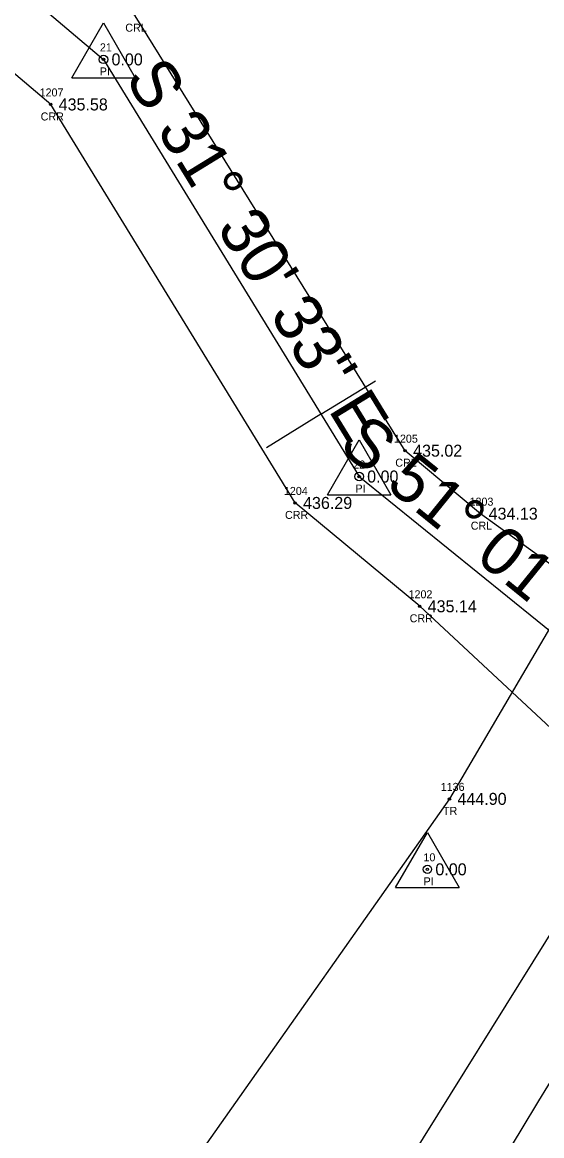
# Model space of a CAD drawing. Extents: x 1762456 to 1764480, y 822234 to 826541.
# Drawn here: x 1763387.7 to 1763452.5, y 824767.8 to 824906.9 of the extents above; entities that cross this region are included whole.
import ezdxf

# ---------------------------------------------------------------- set-up
doc = ezdxf.new("R2010")
doc.units = 0
for name, color, linetype in [('RD_EX_H2O', 7, 'Continuous'), ('RD_EX_H2O_txCode', 7, 'Continuous'), ('RD_EX_Road', 7, 'Continuous'), ('RD_EX_TX_H2O_ELEV', 7, 'Continuous'), ('RD_EX_TX_VEG_ELEV', 7, 'Continuous'), ('RD_EX_VEG', 7, 'Continuous'), ('RD_EX_VEG_txCode', 7, 'Continuous'), ('RD_HC_Cl', 7, 'Continuous'), ('RD_HC_Data', 7, 'Continuous'), ('RD_HC_Data_Tic', 7, 'Continuous'), ('RD_HC_Survey_ELEV', 7, 'Continuous'), ('RD_HC_txCode', 7, 'Continuous'), ('RD_SMD_Locator', 7, 'Continuous')]:
    doc.layers.add(name, color=color, linetype=linetype)

msp = doc.modelspace()

# ---------------------------------------------------------------- linework, layer by layer
at = {"layer": 'RD_EX_H2O'}
for points in [[(1763469.64, 824827.68), (1763444.91, 824845.55), (1763435.48, 824853.42), (1763401.74, 824907.76), (1763323.19, 824974.27), (1763226.75, 825015.18), (1763219.02, 825018.48), (1763206.39, 825014.43), (1763109.02, 824967.64), (1763091.9, 824957.32), (1763081.74, 824947.35), (1763046.14, 824865.15)], [(1763459.77, 824813.09), (1763437.3, 824833.98), (1763421.73, 824846.89), (1763391.2, 824896.67), (1763313.16, 824962.88), (1763227.9, 824997.52), (1763208.46, 824998.22), (1763114.18, 824952.92), (1763092.86, 824935.95), (1763064.35, 824852.13)]]:
    msp.add_lwpolyline(points, dxfattribs=at)
at = {"layer": 'RD_EX_Road'}
msp.add_lwpolyline([(1763458.16, 824800.38), (1763431, 824756.75), (1763406.01, 824711.9), (1763384.24, 824666.74), (1763362.81, 824620.84), (1763342.79, 824575), (1763324.89, 824528.78), (1763288.3, 824435.22), (1763252.09, 824341.05), (1763216.31, 824245.88), (1763180.37, 824152.33)], dxfattribs=at)
at = {"layer": 'RD_EX_VEG'}
msp.add_lwpolyline([(1763566.8, 824996.31), (1763552.48, 824977.49), (1763517.79, 824940.66), (1763441.02, 824809.92), (1763409.91, 824765.77), (1763387.31, 824719.59), (1763364.33, 824675.15), (1763345.2, 824627.76), (1763325.76, 824580.46), (1763306.34, 824535.9), (1763266.94, 824443.24), (1763235.97, 824345.2), (1763198.02, 824250.85), (1763166.5, 824157.97)], dxfattribs=at)
at = {"layer": 'RD_HC_Cl'}
for p, q in [((1763319.55, 824968.55), (1763397.8, 824902.3)), ((1763397.8, 824902.3), (1763429.74, 824850.19)), ((1763429.74, 824850.19), (1763465.36, 824821.37))]:
    msp.add_line(p, q, dxfattribs=at)
msp.add_arc((1764677.02, 824029.63), 1432.39, 137.05318, 159.11763, dxfattribs=at)
at = {"layer": 'RD_HC_Data'}
for p, q in [((1763393.83, 824900), (1763397.8, 824906.88)), ((1763397.8, 824906.88), (1763401.77, 824900)), ((1763393.83, 824900), (1763401.77, 824900)), ((1763425.77, 824847.89), (1763429.74, 824854.77)), ((1763429.74, 824854.77), (1763433.71, 824847.89)), ((1763425.77, 824847.89), (1763433.71, 824847.89)), ((1763434.29, 824798.83), (1763438.26, 824805.71)), ((1763438.26, 824805.71), (1763442.23, 824798.83)), ((1763434.29, 824798.83), (1763442.23, 824798.83))]:
    msp.add_line(p, q, dxfattribs=at)
for centre in [(1763397.8, 824902.3), (1763429.74, 824850.19), (1763438.26, 824801.12)]:
    msp.add_circle(centre, 0.529, dxfattribs=at)
at = {"layer": 'RD_HC_Data_Tic'}
for q in [(1763431.79, 824862.15), (1763418.15, 824853.79)]:
    msp.add_line((1763424.97, 824857.97), q, dxfattribs=at)
at = {"layer": 'RD_SMD_Locator'}
for centre in [(1763397.8, 824902.3), (1763391.2, 824896.67), (1763435.48, 824853.42), (1763429.74, 824850.19), (1763421.73, 824846.89), (1763444.91, 824845.55), (1763437.3, 824833.98), (1763441.02, 824809.92), (1763438.26, 824801.12)]:
    msp.add_circle(centre, 0.15, dxfattribs=at)

# ---------------------------------------------------------------- texts
at = {"layer": 'RD_EX_H2O_txCode'}
for s, p in [('CRL', (1763400.52, 824905.76)), ('1207', (1763389.82, 824897.67)), ('CRR', (1763389.95, 824894.67)), ('1205', (1763434.09, 824854.42)), ('CRL', (1763434.25, 824851.42)), ('1204', (1763420.34, 824847.89)), ('1203', (1763443.53, 824846.55)), ('CRR', (1763420.48, 824844.89)), ('CRL', (1763443.68, 824843.55)), ('1202', (1763435.91, 824834.98)), ('CRR', (1763436.05, 824831.98))]:
    msp.add_text(s, height=1, dxfattribs=at).set_placement(p)
at = {"layer": 'RD_EX_TX_H2O_ELEV'}
for s, p in [('435.58', (1763392.2, 824895.92)), ('435.02', (1763436.48, 824852.67)), ('436.29', (1763422.73, 824846.14)), ('434.13', (1763445.91, 824844.8)), ('435.14', (1763438.3, 824833.23))]:
    msp.add_text(s, height=1.5, dxfattribs=at).set_placement(p)
at = {"layer": 'RD_EX_TX_VEG_ELEV'}
msp.add_text('444.90', height=1.5, dxfattribs=at).set_placement((1763442.02, 824809.17))
at = {"layer": 'RD_EX_VEG_txCode'}
for s, p in [('1136', (1763439.93, 824810.92)), ('TR', (1763440.22, 824807.92))]:
    msp.add_text(s, height=1, dxfattribs=at).set_placement(p)
at = {"layer": 'RD_HC_Data'}
for s, rotation, p in [('S 31%%d 30\' 33" E', 301.509, (1763400.39, 824899.99)), ('S 51%%d 01\' 52" E', 321.0311, (1763427, 824853.69))]:
    msp.add_text(s, height=6, rotation=rotation, dxfattribs=at).set_placement(p)
at = {"layer": 'RD_HC_Survey_ELEV'}
for p in [(1763398.8, 824901.55), (1763430.74, 824849.44), (1763439.26, 824800.37)]:
    msp.add_text('0.00', height=1.5, dxfattribs=at).set_placement(p)
at = {"layer": 'RD_HC_txCode'}
for s, p in [('21', (1763397.35, 824903.3)), ('PI', (1763397.33, 824900.3)), ('22', (1763429.01, 824851.19)), ('PI', (1763429.27, 824848.19)), ('10', (1763437.77, 824802.12)), ('PI', (1763437.79, 824799.12))]:
    msp.add_text(s, height=1, dxfattribs=at).set_placement(p)

doc.saveas('drawing.dxf')
